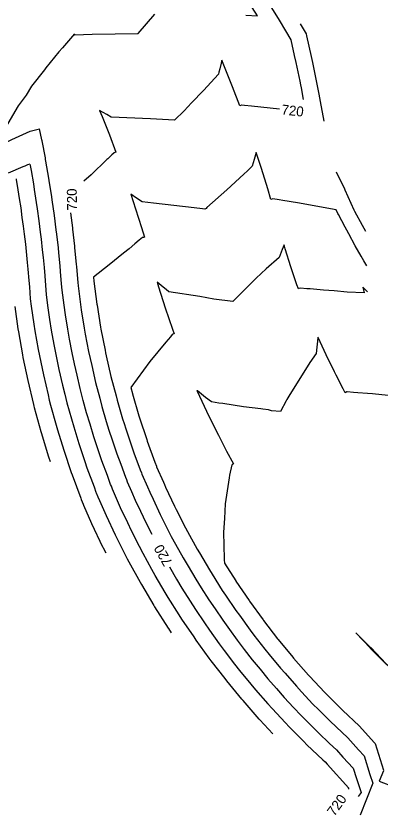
# Model space of a CAD drawing. Extents: x 1487507 to 1489130, y 497211 to 499439.
# Drawn here: x 1488567.6 to 1488655.8, y 499071.8 to 499265.5 of the extents above; entities that cross this region are included whole.
import ezdxf

# ---------------------------------------------------------------- set-up
doc = ezdxf.new("R2010")
doc.units = 0
for name, color, linetype in [('Prop CMT Ditch DDE', 7, 'Continuous'), ('Prop Drainage Ditch Flow Line', 7, 'Continuous'), ('Prop Drainage Structure Box Number Symbol CELL', 7, 'Continuous'), ('Prop Drainage Structure Pipe Outlet Channel Detail CELL', 7, 'Continuous')]:
    doc.layers.add(name, color=color, linetype=linetype)

msp = doc.modelspace()

# ---------------------------------------------------------------- linework, layer by layer
at = {"layer": 'Prop CMT Ditch DDE'}
for points in [[(1488623.27, 499265.71), (1488626.09, 499265.55), (1488624.85, 499267.64)], [(1488581.7, 499261.04), (1488581.86, 499260.96), (1488586.06, 499261.11), (1488597.19, 499261.29), (1488601.26, 499266.02)], [(1488636.46, 499263.62), (1488637.88, 499261.24), (1488637.99, 499260.74), (1488639.12, 499255.76), (1488639.43, 499254.25), (1488640.26, 499250.27), (1488640.98, 499246.61), (1488641.33, 499244.78), (1488642.17, 499240.04)], [(1488581.78, 499261.19), (1488578.9, 499257.79), (1488578.04, 499256.88), (1488574.86, 499252.95), (1488574.56, 499252.52), (1488571.42, 499248.53), (1488570.06, 499246.38), (1488568.13, 499243.78), (1488565.69, 499239.52), (1488565.12, 499238.7), (1488564.79, 499238.21), (1488564.13, 499236.61), (1488563.02, 499235.42), (1488562.11, 499234.38), (1488561.31, 499233.45), (1488560.52, 499232.45), (1488562.54, 499233.57), (1488566.62, 499235.63), (1488571.03, 499237.63), (1488573.36, 499238.15)], [(1488629.86, 499091.53), (1488626.69, 499094.92), (1488626.55, 499095.09), (1488622.62, 499099.57), (1488622.31, 499099.94), (1488618.68, 499104.34), (1488618.26, 499104.9), (1488614.9, 499109.23), (1488614.44, 499109.88), (1488611.28, 499114.23), (1488610.75, 499115.01), (1488607.81, 499119.34), (1488607.17, 499120.36), (1488604.51, 499124.55), (1488603.78, 499125.8), (1488601.37, 499129.86), (1488600.57, 499131.33), (1488598.4, 499135.25), (1488597.55, 499136.94), (1488595.6, 499140.73), (1488594.72, 499142.62), (1488592.98, 499146.29), (1488591.72, 499149.16), (1488591.01, 499150.79), (1488590.73, 499151.51), (1488590.56, 499151.93), (1488589.77, 499154.13), (1488588.44, 499157.69), (1488587.63, 499160.15), (1488586.49, 499163.51), (1488585.56, 499166.57), (1488584.74, 499169.36), (1488583.94, 499172.31), (1488583.17, 499175.26), (1488582.45, 499178.43), (1488581.79, 499181.19), (1488581.24, 499183.84), (1488580.6, 499187.15), (1488580.16, 499189.65), (1488579.6, 499193.12), (1488579.27, 499195.46), (1488578.79, 499199.11), (1488578.69, 499200.58), (1488578.43, 499203.63), (1488578.32, 499204.97), (1488578.01, 499208.14), (1488577.89, 499209.31), (1488577.51, 499212.65), (1488577.4, 499213.67), (1488576.94, 499217.17), (1488576.4, 499220.94), (1488576.3, 499221.69), (1488575.68, 499225.64), (1488575.59, 499226.22), (1488574.87, 499230.34), (1488574.81, 499230.74), (1488574.74, 499231.12), (1488573.95, 499235.27), (1488573.91, 499235.5), (1488573.36, 499238.15)], [(1488652.61, 499204.94), (1488651.89, 499206.16), (1488651.21, 499207.35), (1488649.78, 499209.85), (1488648.22, 499212.7), (1488647.72, 499213.61), (1488647.34, 499214.32), (1488645.72, 499217.42), (1488645.61, 499217.65), (1488645.21, 499218.52), (1488635.83, 499220.23), (1488632.24, 499220.83), (1488631.36, 499220.97), (1488629.87, 499221.21), (1488629.63, 499221.14), (1488629.39, 499221.07), (1488628.64, 499223.6), (1488627.07, 499228.6), (1488625.8, 499232.46), (1488625.3, 499230.77), (1488624.79, 499229.12), (1488623.67, 499228.03), (1488622.78, 499227.22), (1488618.69, 499223.39), (1488613.84, 499219.08), (1488613.65, 499218.91), (1488613.4, 499218.7), (1488612.83, 499218.77), (1488610.76, 499219.01), (1488600.9, 499220.18), (1488598.17, 499220.45), (1488596.8, 499221.39), (1488595.45, 499222.31), (1488596.61, 499218.8), (1488598.03, 499214.25), (1488598.72, 499211.95), (1488598.48, 499211.88), (1488598.24, 499211.81), (1488597.49, 499211.18), (1488596.43, 499210.3), (1488595.01, 499209.11), (1488593.69, 499208.04), (1488590.21, 499205.19), (1488586.42, 499202.23), (1488586.51, 499201.25), (1488586.51, 499201.22), (1488587.23, 499195.7), (1488587.27, 499195.43), (1488588.12, 499190.12), (1488588.2, 499189.64), (1488589.19, 499184.54), (1488589.33, 499183.88), (1488589.5, 499183.18), (1488590.64, 499178.13), (1488591.86, 499173.44), (1488592.13, 499172.42), (1488593.45, 499167.91), (1488593.81, 499166.75), (1488594.24, 499165.47), (1488595.67, 499161.12), (1488596.21, 499159.66), (1488597.71, 499155.54), (1488598.01, 499154.75), (1488598.14, 499154.43), (1488599.46, 499151.37), (1488600.03, 499150.07), (1488600.82, 499148.41), (1488602.56, 499144.69), (1488603.47, 499142.91), (1488605.25, 499139.38), (1488606.29, 499137.5), (1488608.12, 499134.16), (1488609.3, 499132.17), (1488611.15, 499129.02), (1488612.48, 499126.92), (1488614.34, 499123.97), (1488615.83, 499121.78), (1488617.69, 499119.02), (1488619.31, 499116.79), (1488621.19, 499114.18), (1488622.93, 499111.94), (1488624.84, 499109.45), (1488626.73, 499107.15), (1488628.65, 499104.83), (1488630.71, 499102.48), (1488632.59, 499100.33), (1488634.84, 499097.92), (1488636.67, 499095.95), (1488639.12, 499093.49), (1488640.89, 499091.71), (1488643.56, 499089.18), (1488645.24, 499087.6), (1488646.82, 499085.85), (1488649.29, 499083.15), (1488650.06, 499080.66), (1488651.19, 499077.3)], [(1488571.02, 499229.64), (1488570.41, 499229.42), (1488569.76, 499229.17), (1488569.25, 499228.96), (1488565.77, 499227.45)], [(1488571.02, 499229.64), (1488571.08, 499229.29), (1488571.27, 499228.11), (1488571.84, 499224.82), (1488572.04, 499223.46), (1488572.54, 499220.35), (1488572.73, 499218.81), (1488573.16, 499215.89), (1488573.51, 499213.17), (1488573.7, 499211.43), (1488573.99, 499208.88), (1488574.18, 499206.97), (1488574.42, 499204.59), (1488574.59, 499202.52), (1488574.78, 499200.24), (1488574.94, 499198.05), (1488575.29, 499195.34), (1488575.77, 499191.97), (1488576.19, 499189.41), (1488576.8, 499185.9), (1488577.27, 499183.48), (1488578.02, 499179.85), (1488578.93, 499176.06), (1488579.44, 499173.83), (1488579.98, 499171.74), (1488581.04, 499167.84), (1488581.61, 499165.9), (1488582.84, 499161.89), (1488584.33, 499157.49), (1488584.82, 499155.98), (1488586.55, 499151.36), (1488586.99, 499150.13), (1488587.08, 499149.9), (1488587.45, 499148.97), (1488587.85, 499148.06), (1488589.46, 499144.4), (1488591.67, 499139.73), (1488592.13, 499138.76), (1488594.59, 499133.95), (1488594.98, 499133.19), (1488597.71, 499128.24), (1488598, 499127.71), (1488601.01, 499122.62), (1488601.19, 499122.32), (1488604.52, 499117.08), (1488604.55, 499117.03), (1488605.25, 499116)], [(1488567.64, 499226.08), (1488567.67, 499225.88), (1488568.1, 499223.43), (1488568.41, 499221.28), (1488568.77, 499219.02), (1488569.07, 499216.69), (1488569.37, 499214.61), (1488569.62, 499212.68), (1488569.9, 499210.2), (1488570.1, 499208.44), (1488570.36, 499205.8), (1488570.51, 499204.2), (1488570.75, 499201.41), (1488570.87, 499199.91), (1488571.08, 499197), (1488571.31, 499195.23), (1488571.94, 499190.82), (1488572.21, 499189.17), (1488573, 499184.65), (1488573.3, 499183.13), (1488574.26, 499178.51), (1488575.41, 499173.69), (1488575.7, 499172.39), (1488576.02, 499171.18), (1488577.35, 499166.31), (1488577.66, 499165.23), (1488579.18, 499160.27), (1488581.02, 499154.83), (1488581.21, 499154.27), (1488583.33, 499148.6), (1488583.42, 499148.33), (1488583.44, 499148.28), (1488583.89, 499147.15), (1488583.97, 499146.95), (1488585.93, 499142.51), (1488588.62, 499136.83), (1488588.65, 499136.78), (1488589.38, 499135.36)], [(1488652.78, 499198.7), (1488651.66, 499199.79), (1488651.95, 499198.43), (1488647.87, 499198.62), (1488644.67, 499198.91), (1488642.12, 499199.04), (1488638.9, 499199.36), (1488638.03, 499199.43), (1488636.51, 499199.58), (1488636.15, 499199.45), (1488636.04, 499199.41), (1488635.68, 499200.38), (1488634.19, 499204.74), (1488632.81, 499209.12), (1488632.55, 499210.06), (1488632.08, 499208.9), (1488631.39, 499206.99), (1488628.18, 499204.22), (1488625.83, 499201.99), (1488620.15, 499196.35), (1488615.53, 499196.92), (1488612.15, 499197.5), (1488604.65, 499198.69), (1488604.02, 499199.2), (1488602.91, 499200.13), (1488602.23, 499200.69), (1488601.86, 499201), (1488602.17, 499199.91), (1488603.79, 499194.76), (1488605.54, 499189.65), (1488605.96, 499188.51), (1488605.6, 499188.38), (1488605.49, 499188.34), (1488605.03, 499187.78), (1488603.89, 499186.44), (1488600.02, 499181.74), (1488595.42, 499175.51), (1488595.81, 499174), (1488595.83, 499173.95), (1488597.4, 499168.58), (1488597.47, 499168.37), (1488597.54, 499168.14), (1488599.28, 499162.83), (1488599.44, 499162.42), (1488601.28, 499157.34), (1488601.65, 499156.36), (1488601.7, 499156.25), (1488603.33, 499152.48), (1488603.56, 499151.96), (1488603.87, 499151.3), (1488606.04, 499146.67), (1488606.43, 499145.9), (1488608.68, 499141.45), (1488609.16, 499140.58), (1488611.49, 499136.3), (1488612.06, 499135.35), (1488614.47, 499131.25), (1488615.13, 499130.21), (1488617.6, 499126.29), (1488618.36, 499125.16), (1488620.89, 499121.42), (1488621.74, 499120.25), (1488624.33, 499116.66), (1488625.26, 499115.46), (1488627.92, 499112), (1488628.95, 499110.76), (1488631.66, 499107.46), (1488632.79, 499106.17), (1488635.54, 499103.03), (1488636.77, 499101.71), (1488639.55, 499098.73), (1488640.9, 499097.37), (1488643.7, 499094.56), (1488645.17, 499093.17), (1488647.98, 499090.51), (1488650.62, 499087.59), (1488651.95, 499086.13), (1488653.33, 499081.67), (1488654.06, 499079.51), (1488650.96, 499071.8)], [(1488567.33, 499195.11), (1488568.11, 499189.67), (1488568.23, 499188.93), (1488569.2, 499183.4), (1488569.32, 499182.77), (1488570.49, 499177.17), (1488571.89, 499171.32), (1488571.97, 499170.95), (1488572.06, 499170.62), (1488573.65, 499164.78), (1488573.71, 499164.56), (1488575.52, 499158.64), (1488575.89, 499157.55)], [(1488657.79, 499173.57), (1488654, 499173.95), (1488652.72, 499174), (1488650.43, 499174.21), (1488649.33, 499174.29), (1488647.83, 499174.44), (1488647.73, 499174.38), (1488647.39, 499174.2), (1488646.86, 499175.17), (1488645.15, 499178.44), (1488644.73, 499179.26), (1488642.71, 499183.39), (1488640.8, 499187.57), (1488640.76, 499187.66), (1488640.74, 499187.55), (1488640.34, 499183.75), (1488638.76, 499181.52), (1488636.96, 499178.58), (1488633.93, 499173.81), (1488633.23, 499172.55), (1488633.05, 499172.26), (1488631.68, 499169.68), (1488629.53, 499169.83), (1488628.75, 499170.06), (1488627.42, 499170.22), (1488626.96, 499170.29), (1488622.73, 499170.76), (1488617.74, 499171.56), (1488616.73, 499171.68), (1488614.95, 499171.96), (1488613.54, 499173.07), (1488611.59, 499174.63), (1488611.54, 499174.68), (1488611.5, 499174.71), (1488611.54, 499174.61), (1488613.79, 499169.7), (1488616.16, 499164.84), (1488616.65, 499163.88), (1488618.65, 499160.05), (1488620.34, 499157), (1488620.06, 499156.84), (1488619.9, 499156.75), (1488619.32, 499154.22), (1488619.22, 499153.56), (1488618.28, 499147.23), (1488618.1, 499143.69), (1488617.86, 499140.36), (1488618.05, 499133.94), (1488618.06, 499133.66), (1488618.14, 499132.91), (1488620.86, 499128.6), (1488620.9, 499128.54), (1488624.09, 499123.82), (1488624.17, 499123.7), (1488627.47, 499119.13), (1488627.59, 499118.98), (1488631, 499114.55), (1488631.16, 499114.36), (1488634.67, 499110.09), (1488634.87, 499109.87), (1488638.49, 499105.74), (1488638.71, 499105.5), (1488642.43, 499101.51), (1488642.68, 499101.26), (1488646.51, 499097.4), (1488646.78, 499097.15), (1488650.71, 499093.43), (1488654.42, 499089.33), (1488654.62, 499089.12), (1488656.61, 499082.68)], [(1488656.65, 499082.56), (1488655.62, 499080), (1488659.35, 499078.59)], [(1488651.19, 499077.3), (1488650.5, 499076.33)]]:
    msp.add_lwpolyline(points, dxfattribs=at)
msp.add_lwpolyline([(1488653.52, 499112.2), (1488653.48, 499112.24), (1488649.97, 499115.97), (1488653.36, 499112.57), (1488653.64, 499112.31), (1488657.26, 499108.48), (1488657.35, 499108.39), (1488657.74, 499107.95), (1488657.32, 499108.36)], close=True, dxfattribs=at)
at = {"layer": 'Prop Drainage Ditch Flow Line'}
for points in [[(1488623.33, 499278.07), (1488625.72, 499273.99), (1488626.2, 499273.18), (1488628.51, 499269.25), (1488629.54, 499267.53), (1488631.33, 499264.5), (1488632.87, 499261.92), (1488634.17, 499259.73), (1488635.02, 499255.94), (1488635.39, 499254.31), (1488636.34, 499249.72), (1488636.52, 499248.88), (1488636.67, 499248.1), (1488637.2, 499245.34)], [(1488631.45, 499242.96), (1488624.67, 499243.68), (1488622.97, 499243.84), (1488622.29, 499243.9), (1488622.26, 499243.89), (1488621.82, 499243.73), (1488620.06, 499248.35), (1488618.12, 499253.21), (1488617.45, 499254.84), (1488617.29, 499254.1), (1488616.98, 499252.75), (1488616.79, 499251.9), (1488616.68, 499251.44), (1488613.03, 499247.47), (1488610.13, 499244.48), (1488608.34, 499242.59), (1488606.01, 499240.27), (1488600.17, 499240.61), (1488590.7, 499240.98), (1488589.62, 499241.63), (1488587.86, 499242.65), (1488588.48, 499241.17), (1488590.24, 499236.74), (1488591.83, 499232.54), (1488591.81, 499232.53), (1488591.36, 499232.37), (1488591.29, 499232.29), (1488590.88, 499231.9), (1488589.86, 499230.93), (1488589.66, 499230.74), (1488585.8, 499227.06), (1488584.1, 499225.52)], [(1488652.37, 499213.27), (1488651.55, 499214.76), (1488649.73, 499218.17), (1488649.57, 499218.48), (1488647.34, 499223.33), (1488647.24, 499223.53), (1488645.26, 499227.68)], [(1488580.81, 499217.84), (1488581.29, 499214.16), (1488581.32, 499213.88), (1488581.79, 499209.75), (1488581.83, 499209.31), (1488582.23, 499205.35), (1488582.28, 499204.74), (1488582.6, 499200.92), (1488582.65, 499200.16), (1488583.25, 499195.58), (1488583.44, 499194.27), (1488584.14, 499189.88), (1488584.4, 499188.39), (1488585.22, 499184.19), (1488585.56, 499182.53), (1488585.97, 499180.81), (1488586.9, 499176.7), (1488587.9, 499172.87), (1488588.44, 499170.89), (1488589.51, 499167.24), (1488590.15, 499165.13), (1488590.94, 499162.81), (1488592.05, 499159.41), (1488592.99, 499156.89), (1488594.14, 499153.74), (1488594.37, 499153.13), (1488594.57, 499152.61), (1488595.59, 499150.27), (1488596.51, 499148.18), (1488597.77, 499145.52), (1488599.08, 499142.71), (1488600.51, 499139.93), (1488600.53, 499139.89)], [(1488604.78, 499131.95), (1488606.54, 499128.98), (1488607.83, 499126.78), (1488609.82, 499123.64), (1488611.07, 499121.66), (1488613.29, 499118.39), (1488614.48, 499116.63), (1488616.87, 499113.33), (1488618.05, 499111.71), (1488620.59, 499108.42), (1488621.76, 499106.89), (1488624.52, 499103.55), (1488625.63, 499102.2), (1488628.63, 499098.78), (1488629.64, 499097.63), (1488632.9, 499094.13), (1488633.79, 499093.18), (1488637.35, 499089.6), (1488638.08, 499088.86), (1488641.96, 499085.2), (1488642.5, 499084.68), (1488643.02, 499084.11), (1488648.27, 499078.36)], [(1488648.27, 499078.36), (1488648.07, 499078.08)]]:
    msp.add_lwpolyline(points, dxfattribs=at)

# ---------------------------------------------------------------- texts
at = {"layer": 'Prop Drainage Structure Box Number Symbol CELL'}
for rotation, p in [(353.7812, (1488631.84, 499241.7)), (91.0567, (1488582.43, 499218.39)), (119.5903, (1488605.63, 499133.03))]:
    msp.add_text('720', height=2.4, rotation=rotation, dxfattribs=at).set_placement(p)
at = {"layer": 'Prop Drainage Structure Pipe Outlet Channel Detail CELL'}
msp.add_text('720', height=2.4, rotation=54.3742, dxfattribs=at).set_placement((1488644.74, 499071.36))

doc.saveas('drawing.dxf')
